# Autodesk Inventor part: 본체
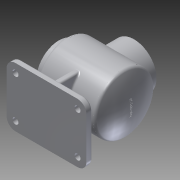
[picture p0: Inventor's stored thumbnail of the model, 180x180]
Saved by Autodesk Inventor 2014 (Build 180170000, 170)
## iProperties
Created: 2016-09
Part Number: 본체
Material: 알루미늄 6061
Document SubType Name: Modeling
Designer: 702
Density: 2.71 g/cm^3
Appearance: 알루미늄 - 평지
Author: 702
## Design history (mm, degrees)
sketch "스케치1"
  geometry: L1 (115, 0)-(5, 0); L2 (5, 0)-(5, 50); L3 (5, 50)-(103.562, 50); A1 r 115 centre (0, 0) between (115, 0) and (103.562, 50)
  constraints: 6 end point, 2 point on circle, 1 centre point, 1 horizontal, 1 parallel, 1 perpendicular
  dimensions: "d6" = 230 diameter of A1; "d7" = 110 distance of L1.start L1.end; "d8" = 50 distance of L1.end L2.end
revolve "회전1" sketch "스케치1" stored, may be unused: angle "d9" = 90 deg
sketch "스케치2"
  geometry: C1 r 50 at (0, 0) reference; C2 r 38 at (0, 0)
  constraints: 1 centre point, 1 coincident
  dimensions: "d10" = 76 diameter of C2
extrude "돌출1" join sketch "스케치2" distance "d11" = 12; taper "d12" = 0 deg
sketch "스케치3"
  geometry: C1 r 38 at (0, 0) reference; C2 r 27 at (0, 0)
  constraints: 1 centre point, 1 coincident
  dimensions: "d13" = 54 diameter of C2
extrude "돌출2" cut sketch "스케치3" distance "d14" = 15; taper "d15" = 0 deg
sketch "스케치5"
  geometry: L1 (5, -50)-(5, 50) reference; L2 (103.562, -50)-(103.562, 50) reference; L3 (103.562, -50)-(103.562, 50) reference; L4 (114.677, 0)-(111.677, 0); L5 (111.677, 0)-(8, 0); L6 (103.562, 50)-(103.562, 47); L7 (5, 50)-(8, 50); L8 (8, 50)-(8, 47); L9 (8, 47)-(101.634, 47); L10 (5, -50)-(8, -50); L11 (8, -50)-(8, -47); L12 (8, 0)-(8, 47); A1 r 115 centre (-3.323, 0) between (111.677, 0) and (101.634, 47); 1 further point
  constraints: 18 end point, 4 perpendicular, 2 parallel, 2 point on circle, 1 centre point, 1 collinear, 1 point on line
  dimensions: "d16" = 3 distance of L4.start L4.end; "d18" = 3 distance of L3.end L6.end; "d19" = 3 distance of L1.end L7.end; "d20" = 3 distance of L7.end L8.end; "d21" = 3 distance of L1.start L10.end; "d22" = 3 distance of L10.end L11.end
revolve "회전2" sketch "스케치5" stored, may be unused: angle "d23" = 90 deg
sketch "스케치6"
  geometry: 1 further point
node "작업 평면1"
sketch "스케치9"
  geometry: 1 further point
node "작업 평면2"
sketch "스케치10"
  geometry: L1 (-103.562, 50)-(-103.562, -50) reference; L2 (-5, 50)-(-5, -50) reference; 1 further point
  node "투영된 루프4"
sketch "스케치11"
  geometry: L1 (-5, 50)-(-5, -50) reference; L2 (-60, 0)-(-60, 50); L3 (-115, 0)-(-60, 0); L4 (-60, 50)-(-127.5, 50); L5 (-127.5, 50)-(-127.5, -50); L6 (-127.5, -50)-(7.5, -50); L7 (7.5, -50)-(7.5, 50); L8 (7.5, 50)-(-60, 50); A1 r 115 centre (3.323, 0) between (-101.634, 47) and (-101.634, -47) reference; A2 r 115 centre (0, 0) between (-103.562, 50) and (-103.562, -50) reference; 1 further point
  constraints: 14 end point, 3 perpendicular, 2 parallel, 1 point on circle
  dimensions: "d34" = 50 distance of L2.start L2.end; "d36" = 55 distance of L3.start L2.start; "d37" = 67.5 distance of L2.end L4.end; "d38" = 100 distance of L4.end L5.end; "d39" = 135 distance of L5.end L6.end; "d40" = 100 distance of L6.end L7.end
sketch "스케치12"
  geometry: L1 (-103.562, 50)-(-103.562, -50) reference; L2 (-5, 50)-(-5, -50) reference; L3 (7, -38)-(7, 38) reference; L4 (7, 0)-(-54, 0); L5 (-54, 0)-(-54, 50); L6 (-54, 50)-(13.5, 50); L7 (13.5, 50)-(13.5, -50); L8 (13.5, -50)-(-121.5, -50); L9 (-121.5, -50)-(-121.5, 50); L10 (-121.5, 50)-(-54, 50); A1 r 115 centre (0, 0) between (-103.562, 50) and (-103.562, -50) reference; 1 further point
  constraints: 14 end point, 4 parallel, 2 perpendicular, 1 midpoint
  dimensions: "d43" = 61 distance of L4.start L4.end; "d44" = 50 distance of L4.end L5.end; "d45" = 67.5 distance of L5.end L6.end; "d46" = 100 distance of L6.end L7.end; "d47" = 135 distance of L7.end L8.end; "d48" = 100 distance of L8.end L9.end
extrude "돌출5" join sketch "스케치12" distance "d49" = 10; taper "d50" = 0 deg
fillet "모깎기1" dims "d69" = 15
sketch "스케치17"
  geometry: L1 (14, -5)-(14, 5) reference; L2 (14, 5)-(94, 5) reference; L3 (54, -5)-(14, -5) reference; L4 (94, -5)-(54, -5) reference; L5 (94, 5)-(94, -5) reference; L6 (14, 5)-(94, 5); L7 (94, -5)-(14, -5); L8 (54, 45)-(49, 45); L9 (54, 0)-(54, 40); L10 (54, 40)-(49, 40); L11 (49, 40)-(49, -40); L12 (49, -40)-(59, -40); L13 (59, -40)-(59, 40); L14 (59, 40)-(49, 40); 1 further point
  constraints: 18 end point, 5 perpendicular, 1 collinear, 1 parallel
  dimensions: "d73" = 5 distance of L8.start L8.end; "d75" = 40 distance of L9.start L9.end; "d76" = 5 distance of L9.end L10.end; "d77" = 80 distance of L10.end L11.end; "d78" = 10 distance of L11.end L12.end; "d79" = 80 distance of L12.end L13.end
extrude "돌출9" join sketch "스케치17" stored distance "d80" = 10; taper "d81" = 0 deg
sketch "스케치18"
  geometry: L1 (0, 22.251)-(35, 22.251) reference; L2 (0, 0)-(0, 22.251) reference; L3 (35, 0)-(0, 0) reference; L4 (35, 0)-(35, 22.251) reference; 1 further point
fillet "모깎기4" dims "d82" = 3
sketch "스케치19"
  geometry: C1 r 5 at (1.5, 35); C2 r 5 at (1.5, -35); C3 r 5 at (106.5, -35); C4 r 5 at (106.5, 35); A1 r 15 centre (106.5, 35) between (121.5, 35) and (106.5, 50) reference; A2 r 15 centre (1.5, 35) between (1.5, 50) and (-13.5, 35) reference; A3 r 15 centre (1.5, -35) between (-13.5, -35) and (1.5, -50) reference; A4 r 15 centre (106.5, -35) between (106.5, -50) and (121.5, -35) reference; 1 further point
  constraints: 4 centre point, 4 coincident
  dimensions: "d84" = 10 diameter of C1; "d85" = 10 diameter of C2; "d86" = 10 diameter of C3; "d87" = 10 diameter of C4
extrude "돌출10" cut sketch "스케치19" distance "d88" = 100; taper "d89" = 0 deg
sketch "스케치20"
  geometry: C1 r 38 at (0, 0) reference; A1 r 32.5 centre (0, 0) between (0, 32.5) and (-32.5, 0); 2 further points
  constraints: 4 point on circle, 1 centre point, 1 coincident
  dimensions: "d90" = 65 diameter of A1
hole "구멍1" sketch "스케치20" at (32.5, 0), (0, 32.5), (-32.5, 0), (0, -32.5) diameter "d91" = 3.242; stored, may be unused: countersink angle "d95" = 90 deg, drill point angle "d97" = 118 deg; dims "d92" = 8, "d93" = 4, "d94" = 2, "d96" = 10
chamfer "모따기1" distance "d106" = 1; stored, may be unused: second distance "d107" = 2, angle "d108" = 45 deg
fillet "모깎기5" dims "d109" = 5
fillet "모깎기6" dims "d110" = 3
fillet "모깎기7" dims "d111" = 2
fillet "모깎기8" dims "d112" = 3
node "작업 평면3"
sketch "스케치22"
  geometry: 2 further points
  constraints: 1 coincident, 1 other
feature "엠보싱1" sketch "스케치22" dims "d114" = 0.5, "d115" = 0
fillet "모깎기9" dims "d116" = 3
fillet "모깎기10" dims "d117" = 3
node "작업 평면4"
sketch "스케치23"
  geometry: L1 (-10, -50)-(-10, 50) reference; L2 (-62, 7.547)-(-62, 34.906) reference; L3 (-91, 7.547)-(-62, 7.547) reference; L4 (-97, -1.887)-(-97, 1.887) reference; L5 (-62, -7.547)-(-91, -7.547) reference; L6 (-62, -34.906)-(-62, -7.547) reference; L7 (-46, -40.566)-(-56, -40.566) reference; L8 (-46, -7.547)-(-46, -40.566) reference; L9 (-11, -7.547)-(-46, -7.547) reference; L10 (-11, 1.887)-(-11, -7.547) reference; L11 (-46, 7.547)-(-17, 7.547) reference; L12 (-46, 34.906)-(-46, 7.547) reference; L13 (-56, 40.566)-(-52, 40.566) reference; L14 (-100.374, 50)-(-100.374, -50) reference; L15 (-5, 45)-(-5, -45) reference; L16 (-5, 0)-(-55, 0); C1 r 38 at (-55, 0); 7 further points
  constraints: 2 end point, 1 centre point, 1 coincident, 1 midpoint, 1 perpendicular, 12 other
  dimensions: "d119" = 50 distance of L16.start L16.end; "d120" = 76 diameter of C1
extrude "돌출11" join sketch "스케치23" stored distance "d121" = 10; taper "d122" = 0 deg
sketch "스케치24"
  geometry: C1 r 38 at (0, 0) reference; C2 r 27 at (0, 0); 1 further point
  constraints: 1 centre point, 1 coincident
  dimensions: "d123" = 54 diameter of C2
extrude "돌출12" cut sketch "스케치24" distance "d124" = 50; taper "d125" = 0 deg
sketch "스케치25"
  geometry: C1 r 38 at (0, 0) reference; A1 r 32.5 centre (0, 0) between (0, 32.5) and (-32.5, 0); 3 further points
  constraints: 4 point on circle, 1 centre point, 1 coincident
  dimensions: "d126" = 65 diameter of A1
hole "구멍3" sketch "스케치25" at (32.5, 0), (0, 32.5), (0, -32.5), (-32.5, 0) diameter "d127" = 3.242; stored, may be unused: countersink angle "d131" = 90 deg, drill point angle "d133" = 118 deg; dims "d128" = 8, "d129" = 4, "d130" = 2, "d132" = 10
node "솔리드1"
node "투영된 루프1"
node "투영된 루프2"
node "투영된 루프5"
node "투영된 루프8"
other parameters: "d24" = 65, "d32" = -82, "d118" = 65
